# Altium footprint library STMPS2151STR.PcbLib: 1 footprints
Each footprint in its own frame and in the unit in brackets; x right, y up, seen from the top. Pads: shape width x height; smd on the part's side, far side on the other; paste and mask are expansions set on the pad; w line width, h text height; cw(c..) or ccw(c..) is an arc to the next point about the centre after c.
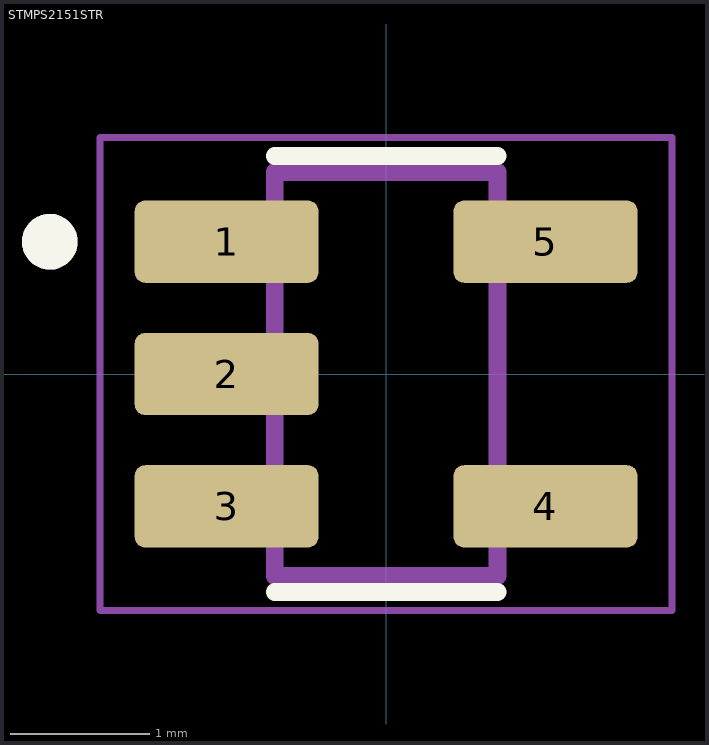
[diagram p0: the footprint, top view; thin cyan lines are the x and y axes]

## STMPS2151STR [mm]
pads (5):
  rrect25% 1.32x0.59 smd: 1(-1.145,0.95) 2(-1.145,0) 3(-1.145,-0.95) 4(1.145,-0.95) 5(1.145,0.95)
Top Overlay:
  circle w0.2: c-2.415,0.95 r0.1
  lines w0.127: -0.8,-1.565 0.8,-1.565 ; -0.8,1.565 0.8,1.565
Mechanical 13:
  circle w0.2: c-2.415,0.95 r0.1
  lines w0.127: -0.8,-1.45 0.8,-1.45 0.8,1.45 -0.8,1.45 -0.8,-1.45
Mechanical 15:
  lines w0.05: -2.055,-1.7 2.055,-1.7 2.055,1.7 -2.055,1.7 -2.055,-1.7
3D body "STMPS2151STR.STEP": height 1.15, standoff 0, extent -1.38,-1.457 1.42,1.444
